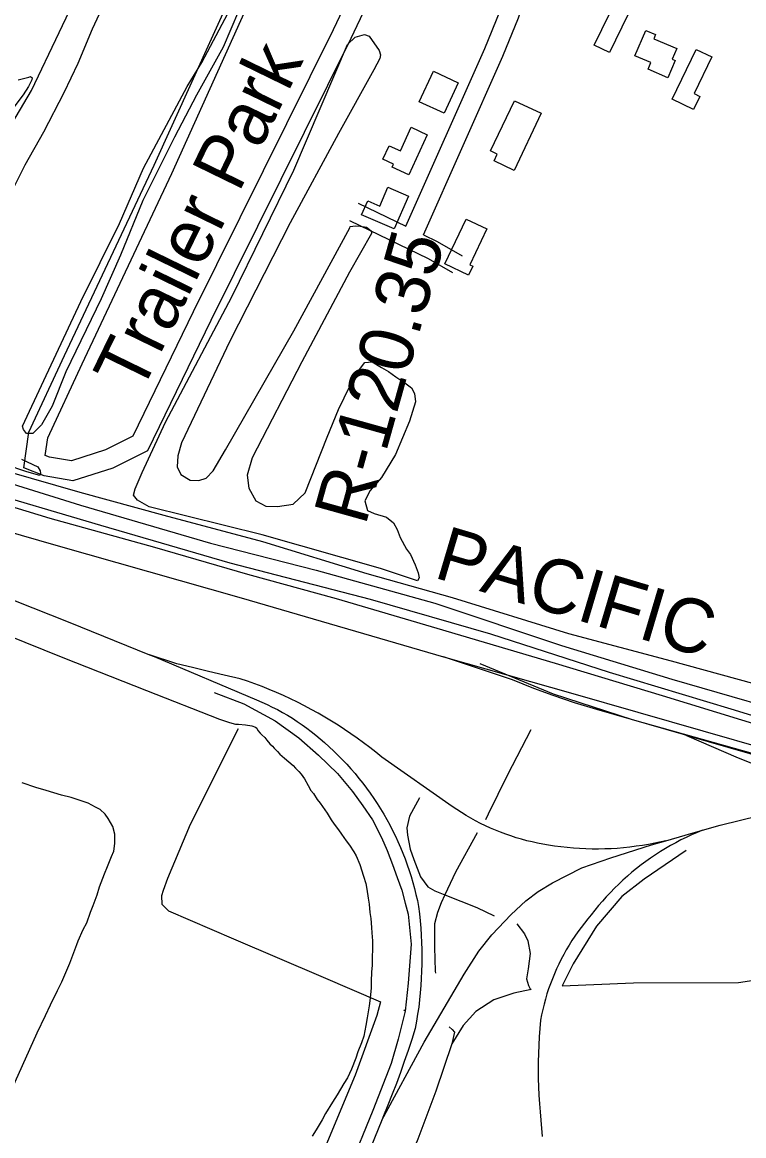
# Model space of a CAD drawing. Extents: x 3567028 to 3605064, y 510945 to 536587.
# Drawn here: x 3589650 to 3590759, y 520355 to 522068 of the extents above; entities that cross this region are included whole.
import ezdxf

# ---------------------------------------------------------------- set-up
doc = ezdxf.new("R2010")
doc.units = 0
for name, color, linetype in [('V-BLDG-OTLN', 7, 'Continuous'), ('V-RAIL-IDEN', 7, 'Continuous'), ('V-RAIL-TRAK', 7, 'Continuous'), ('V-RIVR-RANG-IDEN', 7, 'Continuous'), ('V-ROAD-CNTR', 7, 'Continuous'), ('V-SITE-OTLN-IDEN', 7, 'Continuous'), ('V-SITE-VEGE', 7, 'Continuous'), ('V-TOPO-SHOR', 7, 'Continuous')]:
    doc.layers.add(name, color=color, linetype=linetype)

msp = doc.modelspace()

# ---------------------------------------------------------------- linework, layer by layer
at = {"layer": 'V-BLDG-OTLN'}
for points in [[(3590581.1, 522079.2), (3590552.5, 522021), (3590529.2, 522032.5), (3590552.7, 522080.5), (3590548.4, 522082.6), (3590553.4, 522092.9)], [(3590591.7, 522016), (3590608.5, 522055.2), (3590623.6, 522048.7), (3590620.8, 522042.3), (3590656.2, 522027.1), (3590649.2, 522010.7), (3590653.8, 522008.7), (3590642.5, 521982.3), (3590612, 521995.4), (3590616.3, 522005.5)], [(3590648.8, 521949.3), (3590685.8, 522026), (3590709.9, 522014.4), (3590682.7, 521957.9), (3590691.8, 521953.5), (3590682, 521933.3)], [(3590260.2, 521945.3), (3590282.1, 521992.3), (3590320.2, 521974.6), (3590298.4, 521927.6)], [(3590369.9, 521869.7), (3590406.4, 521946.9), (3590447.4, 521927.6), (3590406.1, 521839.9), (3590375.3, 521854.4), (3590380.2, 521864.8)], [(3590231.1, 521869.7), (3590247.9, 521906.1), (3590272.5, 521894.7), (3590244, 521833), (3590218.4, 521844.8), (3590220.5, 521849.5), (3590204.1, 521857.1), (3590213.7, 521877.8)], [(3590243.4, 521800.3), (3590221.5, 521749.9), (3590171.6, 521771.6), (3590180.9, 521792.9), (3590199.4, 521784.8), (3590212, 521813.9)], [(3590299.3, 521696.1), (3590332.4, 521765), (3590364.2, 521749.7), (3590337.8, 521694.7), (3590342.3, 521692.5), (3590335.7, 521678.7)]]:
    msp.add_lwpolyline(points, close=True, dxfattribs=at)
at = {"layer": 'V-RAIL-TRAK'}
msp.add_line((3590263.3, 520663.4), (3590263.8, 520652.4), dxfattribs=at)
for points in [[(3589514.3, 521317.3), (3589701.3, 521263.5), (3589986.2, 521182.2), (3590297.5, 521091.9), (3590496.2, 521035.3), (3590796.3, 520949), (3591061.1, 520873.3), (3591374.6, 520784.7), (3591658.4, 520710.7), (3591943.9, 520643.4), (3591982.5, 520635), (3592081.6, 520614.3), (3592324.6, 520566)], [(3589499.9, 521232.4), (3589720.1, 521145.4), (3589845.4, 521094.9), (3589852.4, 521092.1), (3590009.9, 521025.3), (3590018, 521021.9), (3590026.1, 521018.3), (3590034.1, 521014.4), (3590042, 521010.4), (3590049.8, 521006.1), (3590057.5, 521001.7), (3590065.1, 520997.1), (3590072.6, 520992.3), (3590079.9, 520987.3), (3590087.1, 520982.1), (3590094.2, 520976.8), (3590101.2, 520971.3), (3590108, 520965.6), (3590114.6, 520959.7), (3590121.8, 520953.3), (3590128.7, 520946.8), (3590135.6, 520940.1), (3590142.2, 520933.3), (3590148.8, 520926.4), (3590155.2, 520919.3), (3590161.4, 520912), (3590167.5, 520904.7), (3590173.4, 520897.2), (3590179.2, 520889.6), (3590184.8, 520881.8), (3590190.2, 520874), (3590195.5, 520866), (3590200.6, 520857.9), (3590205.5, 520849.7), (3590210.2, 520841.5), (3590214.8, 520833.1), (3590219.2, 520824.6), (3590223.4, 520816), (3590227.4, 520807.4), (3590231.3, 520798.6), (3590234.9, 520789.8), (3590238.4, 520780.9), (3590241.7, 520771.9), (3590244.8, 520762.9), (3590247.7, 520753.8), (3590250.3, 520744.6), (3590252.8, 520735.4), (3590255.1, 520726.1), (3590257.3, 520716.8), (3590259.2, 520707.5), (3590260.5, 520696.5), (3590261.6, 520685.5), (3590262.6, 520674.4), (3590263.3, 520663.4)], [(3589996, 521054.1), (3589984.7, 521057.9), (3589960.3, 521063.5), (3589935.9, 521069.3), (3589911.5, 521075.1), (3589887.2, 521080.9), (3589845.4, 521094.9)], [(3592693.1, 520501.7), (3592603, 520509.6), (3592577.8, 520511.3), (3592538.6, 520513.5), (3592506.1, 520518), (3592437.3, 520528.1), (3592380.1, 520539.9), (3592265.4, 520561.2), (3592040.3, 520606.6), (3591838.8, 520650.9), (3591780.6, 520665), (3591554.4, 520721.6), (3591400.5, 520763.1), (3591277.9, 520796.2), (3591095.4, 520848.3), (3590897.2, 520905.5), (3590670.9, 520970.9), (3590666.5, 520972.2), (3590533.3, 521010.9), (3590499.1, 521021), (3590466.1, 521032.2), (3590436.5, 521042.8), (3590403.4, 521056.3), (3590297.5, 521091.9)], [(3590639.2, 520808.7), (3590622.2, 520805), (3590612.7, 520803.2), (3590603.2, 520801.6), (3590593.6, 520800.2), (3590584, 520798.9), (3590574.4, 520797.9), (3590564.7, 520797.1), (3590555.1, 520796.6), (3590545.4, 520796.2), (3590535.8, 520796), (3590526.1, 520796), (3590516.4, 520796.3), (3590506.8, 520796.8), (3590497.1, 520797.4), (3590487.5, 520798.3), (3590477.9, 520799.4), (3590468.3, 520800.7), (3590458.8, 520802.2), (3590450.4, 520803.5), (3590442.1, 520805.1), (3590433.8, 520806.9), (3590425.6, 520808.9), (3590417.4, 520811.1), (3590409.3, 520813.5), (3590401.2, 520816.1), (3590393.2, 520818.8), (3590385.3, 520821.8), (3590377.4, 520825), (3590369.6, 520828.3), (3590362, 520831.8), (3590354.3, 520835.5), (3590346.8, 520839.5), (3590339.4, 520843.5), (3590332.1, 520847.8), (3590324.9, 520852.2), (3590317.8, 520856.8), (3590310.8, 520861.6), (3590202.7, 520937.3), (3590193.4, 520944.9), (3590184, 520952.3), (3590174.5, 520959.5), (3590164.9, 520966.5), (3590155.1, 520973.4), (3590145.3, 520980.1), (3590135.3, 520986.6), (3590125.1, 520992.9), (3590114.9, 520999.1), (3590104.6, 521005), (3590094.1, 521010.8), (3590083.6, 521016.4), (3590072.9, 521021.8), (3590062.2, 521027), (3590051.4, 521032), (3590040.5, 521036.8), (3590029.5, 521041.4), (3590018.4, 521045.9), (3590007.2, 521050.1), (3589996, 521054.1)], [(3590670.9, 520970.9), (3590750.4, 520936.2), (3590859, 520893), (3590991.1, 520839.8), (3591026.1, 520825.2), (3591066.3, 520808.5), (3591109.8, 520790.5), (3591146.2, 520771.4), (3591185.9, 520748.2), (3591202.7, 520738.4), (3591229.6, 520717.7), (3591253.1, 520697.5), (3591266.5, 520685.7)], [(3590202.4, 520378.8), (3590267.5, 520498.8), (3590329.2, 520603.5), (3590351.6, 520638.8), (3590371.8, 520664.1), (3590401.5, 520695.4), (3590423.9, 520716.2), (3590443, 520730.7), (3590464.8, 520744.2), (3590510.3, 520767.1), (3590554.5, 520782.3), (3590617.3, 520802.4), (3590639.2, 520808.7), (3590668.9, 520817.2), (3590695.6, 520824.9), (3590722.7, 520832.6), (3590783.2, 520847.7), (3590817.4, 520853.3), (3590844.3, 520854.5), (3590884.7, 520854.4), (3590914.4, 520851.6), (3590947.5, 520845.4), (3591026.1, 520825.2)], [(3590695.6, 520824.9), (3590687.3, 520821.4), (3590679, 520817.8), (3590670.7, 520814), (3590662.6, 520810), (3590654.6, 520805.8), (3590646.6, 520801.4), (3590638.8, 520796.9), (3590631.1, 520792.2), (3590623.4, 520787.3), (3590615.9, 520782.2), (3590608.5, 520777), (3590601.3, 520771.6), (3590594.1, 520766), (3590587.1, 520760.3), (3590580.2, 520754.4), (3590573.4, 520748.4), (3590566.8, 520742.2), (3590560.3, 520735.8), (3590554, 520729.4), (3590547.8, 520722.7), (3590541.8, 520716), (3590535.9, 520709.1), (3590530.2, 520702.1), (3590524.6, 520694.9), (3590519.3, 520688.6), (3590514.1, 520682.2), (3590509, 520675.6), (3590504.1, 520668.9), (3590499.4, 520662.2), (3590494.9, 520655.3), (3590490.5, 520648.2), (3590486.3, 520641.1), (3590482.3, 520633.9), (3590478.4, 520626.6), (3590474.7, 520619.2), (3590471.2, 520611.7), (3590467.9, 520604.1), (3590464.8, 520596.5), (3590461.9, 520588.7), (3590459.1, 520580.9), (3590456.5, 520573.1), (3590454.2, 520565.1), (3590452, 520557.2), (3590450, 520549.1), (3590448.2, 520541.1), (3590446.7, 520532.9), (3590445.5, 520520.1), (3590444.6, 520507.3), (3590443.8, 520494.5), (3590443.3, 520481.6), (3590443, 520468.7), (3590443, 520455.9), (3590443.1, 520443), (3590443.5, 520430.1), (3590444.1, 520417.3), (3590444.9, 520404.4), (3590445.9, 520391.6), (3590447.2, 520378.8), (3590449.4, 520354.1)], [(3590263.8, 520652.4), (3590264.1, 520641.3), (3590264.2, 520630.2), (3590264.1, 520619.2), (3590263.8, 520608.1), (3590263.3, 520597.1), (3590262.6, 520586), (3590261.7, 520575), (3590260.6, 520564), (3590259.3, 520553), (3590257.7, 520542.1), (3590256, 520531.1), (3590254, 520520.2), (3590248.6, 520503.2), (3590243, 520486.2), (3590237.2, 520469.3), (3590231.2, 520452.4), (3590225, 520435.6), (3590218.6, 520418.9), (3590212, 520402.3), (3590205.2, 520385.8), (3590202.4, 520378.8), (3590158.3, 520271)]]:
    msp.add_lwpolyline(points, dxfattribs=at)
at = {"layer": 'V-ROAD-CNTR'}
for points in [[(3590296.6, 522341.3), (3590154.8, 522042.8), (3589939.5, 521609.1), (3589842.1, 521408.7), (3589789.1, 521382), (3589727.7, 521362.6), (3589683.5, 521369.9), (3589651.9, 521382.1), (3589659.8, 521437.2), (3589714.6, 521555.2), (3589852.5, 521847.7), (3589970.7, 522109.4), (3590085.5, 522343.3), (3590113.2, 522404.3)], [(3590269.5, 522354.2), (3590127.8, 522055.9), (3589912.6, 521622.3), (3589819.5, 521430.9), (3589777.8, 521409.8), (3589725.5, 521393.3), (3589691.5, 521399), (3589685, 521401.5), (3589688.9, 521428.6), (3589741.7, 521542.5), (3589879.7, 521835.2), (3589997.8, 522096.6), (3590112.6, 522330.5), (3590140.5, 522391.9)], [(3590239.7, 521753.9), (3590361, 522027.2), (3590384.6, 522085.1), (3590384.9, 522085.8), (3590363.4, 522093.2), (3590321.1, 522121.6), (3590371.3, 522216.4), (3590410, 522303.3)], [(3590266.8, 521740.9), (3590388.6, 522015.4), (3590412.7, 522074.5), (3590423, 522104.3), (3590376.9, 522120.2), (3590360.2, 522131.4), (3590398.3, 522203.2), (3590437.4, 522291.1)], [(3590166, 521789.5), (3590239.7, 521753.9)], [(3590153, 521762.5), (3590273.9, 521704.1), (3590311.5, 521682.6)], [(3590266.8, 521740.9), (3590287.9, 521730.7), (3590326.4, 521708.6)], [(3590353.5, 521081.2), (3590466.2, 521035), (3590587.5, 520995.2), (3590897.5, 520907.9), (3591238.2, 520806.4), (3591521.7, 520730.4), (3591802.2, 520661.5), (3591977.8, 520621.5), (3592296.3, 520557.1), (3592462.4, 520527.1), (3592550.1, 520517.2), (3592685.3, 520509)]]:
    msp.add_lwpolyline(points, dxfattribs=at)
at = {"layer": 'V-SITE-VEGE'}
for p, q in [((3589624.7, 521125.8), (3589712.3, 521090.8)), ((3589712.3, 521090.8), (3589840.7, 521039.8)), ((3589840.7, 521039.8), (3589953.2, 520996)), ((3589953.2, 520996), (3589968.6, 520990.6)), ((3589968.6, 520990.6), (3589977.5, 520988.3)), ((3589977.5, 520988.3), (3589982.4, 520988.3)), ((3589982.4, 520988.3), (3589992.8, 520987.3)), ((3589992.8, 520987.3), (3590002.8, 520985.5)), ((3590002.8, 520985.5), (3590008.2, 520983.6)), ((3590008.2, 520983.6), (3590010.4, 520981.8)), ((3590010.4, 520981.8), (3590012.2, 520978.6)), ((3590012.2, 520978.6), (3590015.8, 520974.1)), ((3590015.8, 520974.1), (3590018, 520971.8)), ((3590018, 520971.8), (3590022.5, 520967.7)), ((3590022.5, 520967.7), (3590025.7, 520963.6)), ((3590025.7, 520963.6), (3590030.6, 520957.7)), ((3590030.6, 520957.7), (3590034.6, 520954.5)), ((3590034.6, 520954.5), (3590037.3, 520951.3)), ((3590037.3, 520951.3), (3590042.3, 520946.3)), ((3590042.3, 520946.3), (3590045.9, 520942.2)), ((3590045.9, 520942.2), (3590053.1, 520935.8)), ((3590053.1, 520935.8), (3590066.5, 520924.4)), ((3590066.5, 520924.4), (3590070.1, 520920.3)), ((3590070.1, 520920.3), (3590075.1, 520915.3)), ((3590075.1, 520915.3), (3590078.7, 520911.2)), ((3590078.7, 520911.2), (3590083.6, 520904)), ((3590083.6, 520904), (3590089.4, 520894)), ((3589670.6, 520890.5), (3589649.4, 520897.9)), ((3589686.4, 520886.3), (3589670.6, 520890.5)), ((3589710.3, 520878.9), (3589686.4, 520886.3)), ((3590089.4, 520894), (3590093.4, 520886.3)), ((3590093.4, 520886.3), (3590097.4, 520881.3)), ((3589724.7, 520875.2), (3589710.3, 520878.9)), ((3589741.9, 520869.7), (3589724.7, 520875.2)), ((3589750.9, 520866.4), (3589741.9, 520869.7)), ((3589762.1, 520860.5), (3589750.9, 520866.4)), ((3590097.4, 520881.3), (3590103.2, 520872.2)), ((3590103.2, 520872.2), (3590107.7, 520866.7)), ((3590107.7, 520866.7), (3590118.5, 520851.3)), ((3589769.3, 520856.8), (3589762.1, 520860.5)), ((3589777, 520849.5), (3589769.3, 520856.8)), ((3589781.9, 520843.2), (3589777, 520849.5)), ((3590118.5, 520851.3), (3590124.7, 520840.8)), ((3589789.1, 520830.9), (3589781.9, 520843.2)), ((3589792.1, 520818.7), (3589789.1, 520830.9)), ((3590124.7, 520840.8), (3590129.2, 520834.5)), ((3590129.2, 520834.5), (3590135.9, 520825.8)), ((3589792, 520804.7), (3589792.1, 520818.7)), ((3590135.9, 520825.8), (3590140.4, 520819)), ((3590140.4, 520819), (3590148, 520808.6)), ((3589790.6, 520792.9), (3589792, 520804.7)), ((3590148, 520808.6), (3590152.9, 520802.2)), ((3590152.9, 520802.2), (3590159.7, 520791.8)), ((3589780.9, 520769), (3589786.9, 520784.4)), ((3589786.9, 520784.4), (3589790.6, 520792.9)), ((3590159.7, 520791.8), (3590163.2, 520785.4)), ((3590163.2, 520785.4), (3590169, 520772.3)), ((3589776.3, 520757.8), (3589780.9, 520769)), ((3590169, 520772.3), (3590174.3, 520754.2)), ((3589768.5, 520737.9), (3589776.3, 520757.8)), ((3590174.3, 520754.2), (3590177.9, 520742.8)), ((3589764.8, 520725.7), (3589768.5, 520737.9)), ((3590177.9, 520742.8), (3590179.6, 520734.2)), ((3590179.6, 520734.2), (3590181.8, 520720.6)), ((3589758.8, 520709), (3589764.8, 520725.7)), ((3590181.8, 520720.6), (3590183.1, 520711.1)), ((3590183.1, 520711.1), (3590184.3, 520698.5)), ((3589749.1, 520682.4), (3589754.7, 520699.1)), ((3589754.7, 520699.1), (3589758.8, 520709)), ((3590184.3, 520698.5), (3590185.6, 520689)), ((3589743.6, 520672.1), (3589749.1, 520682.4)), ((3590185.6, 520689), (3590186.9, 520675.4)), ((3589735.8, 520655), (3589743.6, 520672.1)), ((3590186.9, 520675.4), (3590187.3, 520667.3)), ((3590187.3, 520667.3), (3590188.1, 520655)), ((3589722.9, 520620.7), (3589733.5, 520649.1)), ((3589733.5, 520649.1), (3589735.8, 520655)), ((3590188.1, 520655), (3590187.8, 520617.1)), ((3589710.5, 520591.8), (3589719.7, 520613.5)), ((3589719.7, 520613.5), (3589722.9, 520620.7)), ((3590187.8, 520617.1), (3590186.9, 520607.1)), ((3589704.1, 520578.3), (3589710.5, 520591.8)), ((3590186.3, 520592.2), (3590186.2, 520582.7)), ((3590186.9, 520607.1), (3590186.3, 520592.2)), ((3589693.1, 520556.2), (3589704.1, 520578.3)), ((3590186.2, 520582.7), (3590184.8, 520566.9)), ((3590184.8, 520566.9), (3590183.3, 520554.7)), ((3589672.9, 520513.4), (3589685.3, 520540)), ((3589685.3, 520540), (3589693.1, 520556.2)), ((3590183.3, 520554.7), (3590180, 520536.2)), ((3590178.1, 520524.5), (3590174.9, 520508.2)), ((3590180, 520536.2), (3590178.1, 520524.5)), ((3589604.1, 520361.1), (3589672.9, 520513.4)), ((3590174.9, 520508.2), (3590171.6, 520497.8)), ((3590171.6, 520497.8), (3590165.7, 520483.9)), ((3590162.4, 520474.4), (3590156, 520457.7)), ((3590165.7, 520483.9), (3590162.4, 520474.4)), ((3590156, 520457.7), (3590149.6, 520444.2)), ((3590149.6, 520444.2), (3590144.1, 520435.2)), ((3590144.1, 520435.2), (3590134, 520418.1)), ((3590126.7, 520406.8), (3590116.2, 520389.3)), ((3590134, 520418.1), (3590126.7, 520406.8)), ((3590116.2, 520389.3), (3590110.7, 520379.3)), ((3590110.7, 520379.3), (3590101.5, 520364)), ((3590101.5, 520364), (3590095.6, 520354.6))]:
    msp.add_line(p, q, dxfattribs=at)
for points in [[(3589628.7, 521902.7), (3589664.1, 521962.5), (3589749.1, 522141.4), (3589750.3, 522146.1), (3589756.3, 522154.5), (3589765.9, 522154.5), (3589779, 522149.7), (3589786.2, 522143.7), (3589789.2, 522133.6), (3589786.8, 522122.8), (3589779, 522103.7), (3589757.4, 522057), (3589735.3, 522004.4), (3589713.7, 521958.9), (3589682.6, 521898.5), (3589653.7, 521847.8), (3589633.6, 521807.8)], [(3589643.2, 521979.1), (3589659.8, 521983.2), (3589662.2, 521984.4), (3589665.1, 521982.1), (3589664.5, 521979.1), (3589659.2, 521969), (3589650.9, 521956), (3589636.6, 521937)], [(3589648.7, 521395.7), (3589673.6, 521383.8), (3589677.2, 521377.9), (3589677.8, 521373.8), (3589676.6, 521370.8), (3589657, 521376.1), (3589589.4, 521398.7)], [(3589544.9, 521385.3), (3589739.4, 521324.7), (3589939.2, 521266.5), (3590101.6, 521224.9), (3590284.3, 521174.4), (3590478.7, 521109), (3590648.3, 521057.3), (3590883, 520989.6)], [(3590983.2, 520936.2), (3590739.6, 521011), (3590552.8, 521067.5), (3590370.2, 521126.3), (3590185.2, 521179.8), (3589969.4, 521235.6), (3589770.8, 521293.9), (3589575.8, 521350.9)]]:
    msp.add_lwpolyline(points, dxfattribs=at)
for points in [[(3589650.2, 521446.5), (3589683.1, 521516.8), (3589739.6, 521638.4), (3589799.5, 521758), (3589836.4, 521843.4), (3589903.5, 521968.9), (3589925.9, 522005.7), (3589966, 522081.2), (3589987.1, 522120.6), (3589991, 522125.2), (3589996.9, 522118.7), (3589982.4, 522084.5), (3589958.7, 522029.3), (3589917.9, 521955.7), (3589883.7, 521890.7), (3589835, 521793.4), (3589800.8, 521709.3), (3589771.2, 521642.3), (3589716.6, 521529.9), (3589695.5, 521477.4), (3589679.1, 521448.5), (3589665.9, 521435.3), (3589656.1, 521435.3), (3589651.5, 521441.2)], [(3590153.3, 521751.7), (3590153.9, 521753.5), (3590162.3, 521754.7), (3590169.4, 521754.1), (3590179, 521752.3), (3590186.2, 521746.9), (3590186.8, 521742.7), (3590152.7, 521683.5), (3590079.6, 521545.3), (3590003.5, 521397.6), (3589995.7, 521371.3), (3589998.1, 521351), (3590008.9, 521331.8), (3590024.4, 521323.4), (3590042.4, 521322.8), (3590066.3, 521326.4), (3590084.9, 521343.7), (3590118.4, 521429.3), (3590135.8, 521472.3), (3590161.5, 521524.9), (3590176.5, 521544.1), (3590187.9, 521545.3), (3590202.2, 521536.9), (3590213, 521530.3), (3590224.4, 521522.5), (3590238.1, 521512.9), (3590248.3, 521505.2), (3590253, 521496.8), (3590254.2, 521483.6), (3590245.2, 521454.3), (3590223.7, 521402.9), (3590202.1, 521367.6), (3590184.8, 521347.3), (3590176.4, 521331.7), (3590180.6, 521316.8), (3590190.7, 521312), (3590209.9, 521306.6), (3590220.6, 521297.6), (3590226, 521287.4), (3590230.8, 521275.4), (3590240.3, 521257.5), (3590246.9, 521249.1), (3590254.1, 521233), (3590258.3, 521221), (3590260.1, 521213.2), (3590257.7, 521208.4), (3590200.8, 521227.6), (3590018.4, 521279.2), (3589845, 521322.3), (3589827, 521332.5), (3589821, 521340.3), (3589823.4, 521349.9), (3589834.2, 521375), (3589870.2, 521452.7), (3589972, 521645.3), (3590067.2, 521840.3), (3590149.9, 522033.4), (3590161.8, 522044.8), (3590176.2, 522049), (3590183.4, 522046), (3590198.3, 522024.4), (3590200.7, 522017.3), (3590199.5, 522011.9), (3590190.5, 521994.5), (3590136, 521896.5), (3590061.8, 521758.9), (3589968.9, 521577.1), (3589894.7, 521421), (3589888.7, 521400.7), (3589888.1, 521383.9), (3589893.4, 521372), (3589907.8, 521363.6), (3589921, 521363), (3589932.3, 521366.5), (3589943.1, 521377.9), (3589962.3, 521410.2), (3590067.1, 521593.2)]]:
    msp.add_lwpolyline(points, close=True, dxfattribs=at)
at = {"layer": 'V-TOPO-SHOR'}
msp.add_line((3590238.5, 520546.9), (3590236.7, 520548.3), dxfattribs=at)
for points in [[(3591205.5, 520869.1), (3591079.3, 520900), (3590907.9, 520948.1), (3590756.1, 520994.4), (3590634, 521031.9), (3590469.8, 521081.2), (3590287.8, 521135.2), (3590133.1, 521181), (3589996.7, 521218.4), (3589853.8, 521260), (3589692.5, 521304.6), (3589539.6, 521350.9), (3589366.5, 521401.4), (3589211.1, 521441.2), (3589081.3, 521484.6), (3588932.5, 521525), (3588900.5, 521533.3), (3588875, 521536.3), (3588859, 521538.7), (3588846.5, 521543.4), (3588706, 521590.4), (3588663.9, 521602.8)], [(3589612, 521381.4), (3589626.2, 521377.2), (3589738.3, 521345.1), (3589867.5, 521309.5), (3590019.3, 521269), (3590179.4, 521219.7), (3590311, 521182.9), (3590489.4, 521127.6), (3590647.7, 521085.5), (3590798.9, 521043.9), (3590980.9, 520990.4), (3591141, 520945.2), (3591278.3, 520907)], [(3589944.6, 521036.6), (3589990.2, 521019.4), (3590038.7, 520993.3), (3590074.8, 520967.3), (3590105, 520940.6), (3590134.6, 520912.2), (3590157.6, 520884.3), (3590173.6, 520862.4), (3590188.4, 520841.1), (3590202, 520813.9), (3590210.8, 520793.8), (3590219.1, 520772.4), (3590226.2, 520752.3), (3590233.3, 520732.8), (3590238.6, 520712.7), (3590243.3, 520696.1), (3590247.5, 520649.9), (3590243.3, 520589.5), (3590238.5, 520546.9), (3590227.8, 520503.7), (3590217.2, 520466.4), (3590188.7, 520393.7), (3590152.6, 520304.9), (3590122.3, 520241)], [(3589981.9, 520980.9), (3589907.8, 520833.6), (3589872.9, 520750.7), (3589866.3, 520732.4), (3589864, 520724.1), (3589864.5, 520711.1), (3589874.6, 520701), (3589974.6, 520657.8), (3590112.5, 520599.1), (3590200.7, 520560.9)], [(3590431.9, 520979.4), (3590395.6, 520910.4), (3590366.3, 520849.5), (3590362.1, 520840.7)], [(3590260.3, 520874.7), (3590245, 520846.6), (3590240.9, 520828.5), (3590242.1, 520817.3), (3590246.2, 520795.7), (3590252, 520779.9), (3590262, 520753.5), (3590273.1, 520737.7), (3590284.2, 520731.8), (3590299.5, 520725.6)], [(3590349.3, 520820.8), (3590315.8, 520760.5), (3590299.5, 520725.6), (3590293.6, 520713.1), (3590288.3, 520698.4), (3590283.6, 520680.9), (3590283.6, 520645.1), (3590284.7, 520608.2), (3590284.9, 520605)], [(3590670.4, 520793.7), (3590606, 520749.8), (3590571.4, 520722.9), (3590532.7, 520677.2), (3590497, 520619.3), (3590479.7, 520585.9)], [(3590479.7, 520585.9), (3590589.8, 520590.5), (3590750.9, 520591), (3590784.8, 520595.7), (3590823.5, 520605), (3590858, 520616.1), (3590884.1, 520628.4), (3590913.7, 520642.4), (3590979.3, 520664.6), (3591046.6, 520676.9), (3591070.7, 520682.7), (3591084.7, 520687.4), (3591098.8, 520692.7), (3591112.8, 520699.1), (3591124, 520709.7), (3591132.8, 520719), (3591139.8, 520730.1)], [(3590299.5, 520725.6), (3590348.6, 520706.3), (3590375.3, 520693.5)], [(3590410.1, 520681.1), (3590421.8, 520665.8), (3590427.1, 520654.7), (3590430.6, 520635.4), (3590427.7, 520612), (3590425.3, 520596.2), (3590428.2, 520586.2), (3590430.6, 520580.9), (3590432.3, 520579.8)], [(3590432.3, 520579.8), (3590405.4, 520574.5), (3590374.9, 520564), (3590347.4, 520546.4), (3590327.5, 520524.8), (3590310.4, 520496.4)], [(3590200.7, 520560.9), (3590194.7, 520539.9), (3590161.5, 520448.1), (3590108.8, 520321.5), (3590057.8, 520197.2), (3590048.3, 520178.9), (3590037.1, 520165.3), (3590025.8, 520154.6), (3590009.2, 520148.1), (3589967.2, 520139.9), (3589913.9, 520130.4), (3589888.5, 520125.7), (3589873.7, 520116.8), (3589862.4, 520105.6), (3589845.2, 520084.3), (3589819.8, 520026.3), (3589799, 519988.5), (3589787.2, 519961.2), (3589767, 519933.4), (3589739.8, 519913.3), (3589707.8, 519887.9)], [(3590306.3, 520522.7), (3590311, 520518.6), (3590314.5, 520514.5), (3590310.4, 520496.4), (3590285.8, 520423.8), (3590258.2, 520350), (3590248.2, 520326), (3590247.6, 520316.6), (3590252.9, 520307.3), (3590275.7, 520292), (3590299.2, 520283.8), (3590319.7, 520274.4), (3590332.5, 520260.9), (3590343.6, 520244.5), (3590349.5, 520225.8), (3590349.5, 520209.4), (3590340.7, 520181.3), (3590331.3, 520148.5)]]:
    msp.add_lwpolyline(points, dxfattribs=at)

# ---------------------------------------------------------------- texts
at = {"layer": 'V-RAIL-IDEN'}
msp.add_text('PACIFIC', height=83, rotation=343.4546, dxfattribs=at).set_placement((3590280.5, 521214.2))
at = {"layer": 'V-RIVR-RANG-IDEN'}
msp.add_text('R-120.35', height=83, rotation=74.4043, dxfattribs=at).set_placement((3590177.2, 521291.8))
at = {"layer": 'V-SITE-OTLN-IDEN'}
msp.add_text('Trailer Park', height=83, rotation=64, dxfattribs=at).set_placement((3589831.3, 521493.7))

doc.saveas('drawing.dxf')
